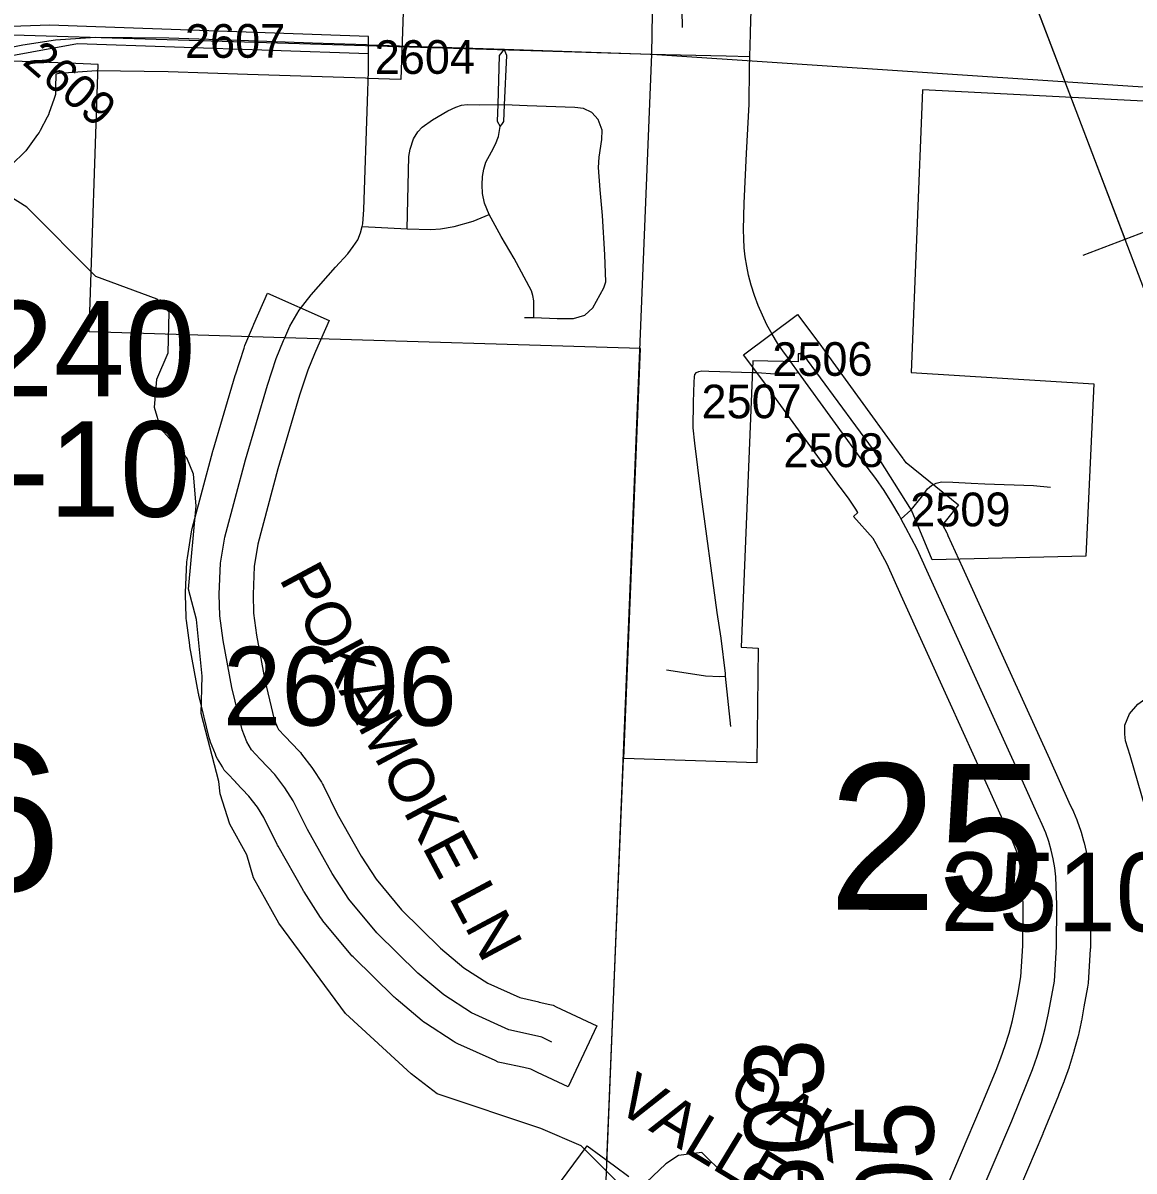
# Model space of a CAD drawing. Extents: x -132.8 to -73.3, y -60 to -26.
# Drawn here: x -123.205 to -122.216, y -43.297 to -42.275 of the extents above; entities that cross this region are included whole.
import ezdxf

# ---------------------------------------------------------------- set-up
doc = ezdxf.new("R2010")
doc.units = 0
for name, color, linetype in [('tdCoCityStreetMajor', 7, 'Continuous'), ('tdCoCityStreetMinor', 7, 'Continuous'), ('tdCoCorpBndry', 7, 'Continuous'), ('tdCoHydroRiver', 7, 'Continuous'), ('tdCoPipe', 7, 'Continuous'), ('tdCoSecRdNmbr', 7, 'Continuous'), ('tdCoSecRdTxt', 7, 'Continuous'), ('tdCoSecRteBand', 7, 'Continuous'), ('tdCoSecRteCL', 7, 'Continuous'), ('tdCoSectLine', 7, 'Continuous'), ('tdCoSectLinePart', 7, 'Continuous'), ('tdCoSectNmbr', 7, 'Continuous'), ('tdCoShieldCoRteHrd', 7, 'Continuous'), ('tdCoStrucSecCoName', 7, 'Continuous'), ('tdCoStrucSecFHWANum', 7, 'Continuous'), ('tdCoSurfAsphalt', 7, 'Continuous'), ('tdCoSurfAsphaltUnbanded', 7, 'Continuous'), ('tdCoSurfConc', 7, 'Continuous'), ('tdCoSurfGravel', 7, 'Continuous')]:
    doc.layers.add(name, color=color, linetype=linetype)

msp = doc.modelspace()

# ---------------------------------------------------------------- linework, layer by layer
at = {"layer": 'tdCoCityStreetMajor'}
for points in [[(-122.5576, -42.3052), (-122.5571, -42.2851), (-122.5567, -42.2723), (-122.5554, -42.2366), (-122.5552, -42.2089), (-122.555, -42.2038), (-122.5547, -42.1912), (-122.5544, -42.1784), (-122.5543, -42.1728), (-122.5537, -42.1347), (-122.5534, -42.1172), (-122.5531, -42.1085), (-122.5531, -42.1076)], [(-122.8973, -42.2947), (-122.8697, -42.2956), (-122.7765, -42.2988), (-122.7075, -42.301), (-122.6466, -42.303), (-122.5787, -42.3047), (-122.5576, -42.3052)], [(-122.5213, -42.5768), (-122.5221, -42.5756), (-122.5278, -42.5681), (-122.5331, -42.5603), (-122.538, -42.5522), (-122.5425, -42.5439), (-122.5466, -42.5354), (-122.5503, -42.5267), (-122.5536, -42.5178), (-122.5565, -42.5088), (-122.5589, -42.4997), (-122.5605, -42.4917), (-122.5618, -42.4836), (-122.5627, -42.4755), (-122.5632, -42.4674), (-122.5633, -42.4592), (-122.5628, -42.4358), (-122.5606, -42.3914), (-122.5584, -42.3475), (-122.5579, -42.3157), (-122.5576, -42.3052)], [(-122.5746, -42.9014), (-122.5793, -42.8566), (-122.5795, -42.8543), (-122.5834, -42.823), (-122.5869, -42.8001), (-122.6014, -42.6926), (-122.6066, -42.6494), (-122.6083, -42.6358), (-122.6079, -42.6127), (-122.6074, -42.5949), (-122.6071, -42.5902), (-122.6066, -42.5882), (-122.6051, -42.5865), (-122.603, -42.5854), (-122.6004, -42.585), (-122.5941, -42.5851), (-122.5555, -42.5864)]]:
    msp.add_lwpolyline(points, dxfattribs=at)
at = {"layer": 'tdCoCityStreetMinor'}
for p, q in [((-122.7822, -42.348), (-122.776, -42.3481)), ((-122.9029, -42.4566), (-122.8629, -42.4586)), ((-122.7582, -42.5374), (-122.7501, -42.5374))]:
    msp.add_line(p, q, dxfattribs=at)
for points in [[(-122.6177, -42.2795), (-122.6185, -42.2339), (-122.619, -42.2019)], [(-122.9029, -42.4566), (-122.9023, -42.4541), (-122.9013, -42.4415), (-122.8981, -42.3451), (-122.8971, -42.318), (-122.8973, -42.3026), (-122.8973, -42.2947)], [(-122.776, -42.3481), (-122.7742, -42.3044), (-122.7765, -42.2988), (-122.7809, -42.3043), (-122.7822, -42.348)], [(-122.8629, -42.4586), (-122.8613, -42.3943), (-122.8601, -42.3876), (-122.857, -42.3784), (-122.8534, -42.3722), (-122.8493, -42.368), (-122.8402, -42.3616), (-122.8265, -42.3536), (-122.8196, -42.3504), (-122.8143, -42.3485), (-122.8094, -42.348), (-122.7985, -42.3481), (-122.7822, -42.348)], [(-122.7822, -42.348), (-122.7826, -42.3627), (-122.7799, -42.3675)], [(-122.7799, -42.3675), (-122.7785, -42.3656), (-122.7766, -42.363), (-122.776, -42.3481)], [(-122.7501, -42.5374), (-122.7292, -42.5383), (-122.7148, -42.5384), (-122.7047, -42.5355), (-122.6974, -42.5288), (-122.6877, -42.5112), (-122.6859, -42.5057), (-122.6867, -42.4816), (-122.689, -42.4466), (-122.691, -42.4238), (-122.6924, -42.4041), (-122.692, -42.3948), (-122.6895, -42.379), (-122.6892, -42.3708), (-122.6927, -42.3614), (-122.6985, -42.3551), (-122.7059, -42.3516), (-122.7135, -42.3505), (-122.7561, -42.349), (-122.776, -42.3481)], [(-122.7898, -42.4457), (-122.7939, -42.4358), (-122.7957, -42.4272), (-122.7961, -42.4194), (-122.7957, -42.4119), (-122.7945, -42.4056), (-122.7926, -42.3991), (-122.7876, -42.3899), (-122.784, -42.3832), (-122.7814, -42.3764), (-122.7799, -42.3675)], [(-122.8629, -42.4586), (-122.8418, -42.4592), (-122.8332, -42.4585), (-122.8208, -42.4564), (-122.8041, -42.4517), (-122.7898, -42.4457)], [(-122.7501, -42.5374), (-122.75, -42.5225), (-122.7508, -42.5179), (-122.7522, -42.5138), (-122.7675, -42.4851), (-122.7791, -42.4655), (-122.7898, -42.4457)], [(-122.9717, -42.5555), (-122.9671, -42.5451), (-122.959, -42.531), (-122.9482, -42.5172), (-122.9267, -42.4926), (-122.9156, -42.4807), (-122.9107, -42.4743), (-122.9067, -42.4684), (-122.9043, -42.462), (-122.9029, -42.4566)], [(-122.414, -42.7087), (-122.405, -42.6975), (-122.3995, -42.69), (-122.3959, -42.6871), (-122.3919, -42.685), (-122.3871, -42.6838), (-122.3771, -42.684), (-122.3607, -42.685), (-122.3486, -42.6854), (-122.3052, -42.6871), (-122.2901, -42.6884)], [(-122.6318, -42.8511), (-122.6106, -42.8543), (-122.5972, -42.8563), (-122.5844, -42.8571), (-122.5793, -42.8566)]]:
    msp.add_lwpolyline(points, dxfattribs=at)
at = {"layer": 'tdCoCorpBndry'}
msp.add_lwpolyline([(-122.132, -42.3489), (-122.404, -42.3348), (-122.4142, -42.5865), (-122.2514, -42.5964), (-122.2585, -42.7499), (-122.3955, -42.7533), (-122.4139, -42.7089), (-122.4476, -42.6552), (-122.5107, -42.5699), (-122.5148, -42.5697), (-122.5148, -42.577), (-122.5551, -42.5761), (-122.5656, -42.8308), (-122.5504, -42.8319), (-122.5514, -42.9337), (-122.6699, -42.9299), (-122.6551, -42.5651), (-122.9717, -42.5555), (-123.146, -42.5502), (-123.1378, -42.3123), (-123.1577, -42.3115), (-123.2378, -42.3084), (-123.1562, -42.2935), (-122.8973, -42.3025), (-122.8973, -42.2947), (-122.8971, -42.2874), (-123.1565, -42.2783), (-123.181, -42.2772), (-123.2152, -42.2786)], dxfattribs=at)
at = {"layer": 'tdCoHydroRiver'}
for points in [[(-122.6755, -43.307), (-122.7078, -43.2746), (-122.7437, -43.2594), (-122.836, -43.2285), (-122.8592, -43.2105), (-122.9177, -43.1569), (-122.9771, -43.0764), (-122.9997, -43.0363), (-123.0054, -43.0157), (-123.0205, -42.9884), (-123.0292, -42.9614), (-123.0305, -42.9503), (-123.0462, -42.8899), (-123.0453, -42.8568), (-123.0503, -42.8062), (-123.0574, -42.7792), (-123.0507, -42.7052), (-123.0531, -42.6768), (-123.059, -42.6624), (-123.082, -42.6366), (-123.0878, -42.6175), (-123.0855, -42.5923), (-123.0755, -42.5689), (-123.0745, -42.5326), (-123.0852, -42.5213), (-123.1399, -42.5009), (-123.2014, -42.4393), (-123.2464, -42.4112)], [(-122.5807, -43.3001), (-122.6006, -43.2806), (-122.6212, -43.2832), (-122.6325, -43.2908), (-122.6616, -43.3184)]]:
    msp.add_lwpolyline(points, dxfattribs=at)
at = {"layer": 'tdCoPipe'}
msp.add_line((-122.186, -42.4535), (-122.2612, -42.4822), dxfattribs=at)
for points in [[(-119.9584, -47.7616), (-119.9471, -47.3844), (-120.3344, -46.3596), (-120.5772, -46.3668), (-120.6441, -46.2979), (-120.7015, -46.0564), (-120.837, -45.9047), (-120.8751, -45.6974), (-120.9717, -45.5088), (-121.2124, -44.6836), (-121.3801, -44.2294), (-121.5957, -43.7643), (-121.8285, -43.2571), (-122.1175, -42.7469), (-122.5487, -41.6141), (-122.6831, -41.5141), (-123.1262, -40.7823)], [(-122.2237, -42.4679), (-122.3309, -42.1863)]]:
    msp.add_lwpolyline(points, dxfattribs=at)
at = {"layer": 'tdCoSecRteBand'}
for points in [[(-122.8664, -42.2657), (-122.8683, -42.3256), (-122.8983, -42.3247), (-122.9, -42.3246), (-122.9479, -42.3231), (-122.9479, -42.3231), (-122.948, -42.3231), (-123.0049, -42.3211), (-123.0049, -42.3211), (-123.0756, -42.3187), (-123.1394, -42.3179), (-123.1726, -42.3203), (-123.1755, -42.3208), (-123.1758, -42.333), (-123.1758, -42.3344), (-123.1759, -42.3391), (-123.1774, -42.3436), (-123.1814, -42.355), (-123.1821, -42.3571), (-123.1832, -42.3592), (-123.1895, -42.371), (-123.1905, -42.3728), (-123.1917, -42.3745), (-123.2008, -42.3871), (-123.2023, -42.3892), (-123.2041, -42.391), (-123.2137, -42.4003)], [(-122.7196, -43.2222), (-122.7468, -43.2094), (-122.7528, -43.2066), (-122.7589, -43.2051), (-122.7787, -43.2007), (-122.7817, -43.2001), (-122.7845, -43.1988), (-122.8178, -43.1838), (-122.8199, -43.1828), (-122.8218, -43.1816), (-122.8465, -43.1655), (-122.848, -43.1645), (-122.8494, -43.1634), (-122.8726, -43.1439), (-122.8735, -43.1431), (-122.8743, -43.1423), (-122.9108, -43.1066), (-122.9119, -43.1055), (-122.9129, -43.1043), (-122.9377, -43.0745), (-122.9388, -43.0731), (-122.9398, -43.0716), (-122.9546, -43.0487), (-122.9551, -43.0479), (-122.9555, -43.0472), (-122.9777, -43.008), (-122.9781, -43.0072), (-122.9785, -43.0064), (-122.9903, -42.9824), (-122.9961, -42.9734), (-123.0036, -42.9635), (-123.0153, -42.9512), (-123.0153, -42.9511), (-123.0154, -42.9511), (-123.0233, -42.9427), (-123.0256, -42.9403), (-123.0273, -42.9373), (-123.0315, -42.9302), (-123.0327, -42.9282), (-123.0335, -42.926), (-123.0377, -42.9154), (-123.0385, -42.9135), (-123.039, -42.9115), (-123.0481, -42.8737), (-123.0483, -42.8729), (-123.0484, -42.8721), (-123.0561, -42.8304), (-123.0562, -42.8297), (-123.0563, -42.829), (-123.0593, -42.8071), (-123.0595, -42.8054), (-123.0595, -42.8038), (-123.06, -42.7843), (-123.06, -42.7833), (-123.06, -42.7822), (-123.0588, -42.7548), (-123.0587, -42.7531), (-123.0584, -42.7515), (-123.0547, -42.7283), (-123.0545, -42.7268), (-123.0541, -42.7253), (-123.0358, -42.6565), (-123.0357, -42.6561), (-123.0356, -42.6557), (-123.0159, -42.5891), (-123.0158, -42.5888), (-123.0157, -42.5884), (-123.008, -42.5647), (-123.0076, -42.5636), (-123.0072, -42.5624), (-123.0005, -42.5464), (-123.0004, -42.5461), (-123.0002, -42.5458), (-122.9992, -42.5433), (-122.987, -42.5159), (-122.9322, -42.5402), (-122.9443, -42.5676), (-122.9452, -42.5697), (-122.9513, -42.5843), (-122.9585, -42.6065), (-122.978, -42.6723), (-122.9957, -42.7392), (-122.9989, -42.7592), (-123, -42.7839), (-122.9996, -42.8007), (-122.9969, -42.8203), (-122.9896, -42.8604), (-122.9811, -42.8953), (-122.9786, -42.9018), (-122.9773, -42.9041), (-122.9717, -42.91), (-122.9589, -42.9235), (-122.9578, -42.9247), (-122.9568, -42.926), (-122.9476, -42.9381), (-122.947, -42.9389), (-122.9465, -42.9398), (-122.9391, -42.9511), (-122.9381, -42.9527), (-122.9372, -42.9543), (-122.9251, -42.9792), (-122.9037, -43.0169), (-122.8904, -43.0375), (-122.8677, -43.0648), (-122.8331, -43.0987), (-122.8122, -43.1162), (-122.791, -43.13), (-122.7626, -43.1428), (-122.7457, -43.1466), (-122.7455, -43.1467), (-122.7453, -43.1467), (-122.7359, -43.1489), (-122.7329, -43.1496), (-122.73, -43.151), (-122.7211, -43.1552), (-122.694, -43.168), (-122.7196, -43.2222)], [(-122.3862, -43.3205), (-122.3523, -43.2408), (-122.3386, -43.2074), (-122.3342, -43.1963), (-122.3304, -43.1854), (-122.327, -43.1744), (-122.324, -43.1632), (-122.3215, -43.152), (-122.3193, -43.1401), (-122.3164, -43.1244), (-122.3146, -43.0966), (-122.3144, -43.061), (-122.3153, -43.0376), (-122.316, -43.0315), (-122.3171, -43.0253), (-122.3185, -43.0191), (-122.3202, -43.013), (-122.3223, -43.007), (-122.3248, -43.0011), (-122.3279, -42.9946), (-122.3281, -42.9942), (-122.3283, -42.9939), (-122.3458, -42.9549), (-122.3805, -42.8783), (-122.4229, -42.7849), (-122.4356, -42.7571), (-122.4452, -42.739), (-122.4478, -42.7342), (-122.4654, -42.7146), (-122.4615, -42.711), (-122.4633, -42.7081), (-122.47, -42.6984), (-122.4774, -42.6885), (-122.4775, -42.6884), (-122.4776, -42.6882), (-122.5387, -42.6039), (-122.5454, -42.5946), (-122.5633, -42.5707), (-122.5152, -42.5348), (-122.4972, -42.5589), (-122.4972, -42.5589), (-122.4971, -42.559), (-122.497, -42.5592), (-122.4901, -42.5687), (-122.4291, -42.6528), (-122.4216, -42.663), (-122.4212, -42.6634), (-122.4209, -42.6639), (-122.4188, -42.6669), (-122.4185, -42.6665), (-122.3719, -42.7042), (-122.3862, -42.722), (-122.3824, -42.7291), (-122.3825, -42.7292), (-122.3822, -42.7297), (-122.3818, -42.7305), (-122.3814, -42.7314), (-122.3683, -42.76), (-122.3683, -42.76), (-122.3683, -42.76), (-122.3259, -42.8535), (-122.3259, -42.8535), (-122.3259, -42.8535), (-122.2911, -42.9302), (-122.2911, -42.9302), (-122.2911, -42.9303), (-122.2737, -42.9689), (-122.2704, -42.9757), (-122.27, -42.9765), (-122.2697, -42.9773), (-122.2666, -42.9847), (-122.2663, -42.9855), (-122.266, -42.9863), (-122.2633, -42.9939), (-122.2631, -42.9947), (-122.2628, -42.9955), (-122.2606, -43.0032), (-122.2604, -43.004), (-122.2602, -43.0049), (-122.2584, -43.0127), (-122.2582, -43.0135), (-122.258, -43.0144), (-122.2567, -43.0223), (-122.2566, -43.0231), (-122.2565, -43.024), (-122.2556, -43.032), (-122.2554, -43.033), (-122.2554, -43.0341), (-122.2544, -43.0593), (-122.2544, -43.06), (-122.2544, -43.0607), (-122.2546, -43.0979), (-122.2546, -43.0988), (-122.2547, -43.0997), (-122.2567, -43.13), (-122.2568, -43.1317), (-122.2571, -43.1334), (-122.2603, -43.151), (-122.2603, -43.151), (-122.2603, -43.151), (-122.2626, -43.1635), (-122.2627, -43.1641), (-122.2629, -43.1646), (-122.2656, -43.177), (-122.2658, -43.1776), (-122.2659, -43.1781), (-122.2692, -43.1904), (-122.2693, -43.1909), (-122.2695, -43.1915), (-122.2732, -43.2036), (-122.2734, -43.2042), (-122.2736, -43.2047), (-122.2778, -43.2167), (-122.278, -43.2172), (-122.2782, -43.2178), (-122.2829, -43.2296), (-122.2829, -43.2297), (-122.283, -43.2299), (-122.2968, -43.2637), (-122.2969, -43.2639), (-122.297, -43.2641), (-122.331, -43.344)], [(-122.7381, -43.3228), (-122.7024, -43.2746), (-122.6783, -43.2924), (-122.6654, -43.302)]]:
    msp.add_lwpolyline(points, dxfattribs=at)
at = {"layer": 'tdCoSecRteCL'}
for points in [[(-123.2049, -42.2947), (-123.1758, -42.2905), (-123.1403, -42.2879), (-123.0749, -42.2887), (-123.0039, -42.2911), (-122.9469, -42.2931), (-122.899, -42.2946), (-122.8973, -42.2947)], [(-122.7339, -43.1823), (-122.7428, -43.1781), (-122.7522, -43.1759), (-122.7722, -43.1715), (-122.8055, -43.1564), (-122.8301, -43.1404), (-122.8533, -43.1209), (-122.8898, -43.0851), (-122.9146, -43.0553), (-122.9294, -43.0324), (-122.9516, -42.9932), (-122.9642, -42.9675), (-122.9716, -42.9562), (-122.9807, -42.9441), (-122.9935, -42.9305), (-123.0014, -42.9222), (-123.0056, -42.915), (-123.0098, -42.9044), (-123.0189, -42.8667), (-123.0266, -42.825), (-123.0295, -42.803), (-123.03, -42.7836), (-123.0288, -42.7562), (-123.0251, -42.733), (-123.0068, -42.6642), (-122.9871, -42.5976), (-122.9795, -42.5739), (-122.9728, -42.5579), (-122.9717, -42.5555)], [(-122.5144, -42.5863), (-122.5213, -42.5768), (-122.5213, -42.5768)], [(-122.5555, -42.5864), (-122.5511, -42.5865), (-122.5356, -42.5875), (-122.5267, -42.5873), (-122.5198, -42.5873), (-122.5144, -42.5863)], [(-122.4231, -42.7169), (-122.4249, -42.7135), (-122.4314, -42.7024), (-122.4383, -42.6915), (-122.4456, -42.6809), (-122.4533, -42.6706), (-122.5144, -42.5863)], [(-122.4231, -42.7169), (-122.4229, -42.7167), (-122.4144, -42.7091), (-122.414, -42.7087)], [(-122.3586, -43.3322), (-122.3246, -43.2523), (-122.3108, -43.2185), (-122.3061, -43.2067), (-122.3019, -43.1948), (-122.2982, -43.1827), (-122.2949, -43.1704), (-122.2921, -43.158), (-122.2898, -43.1455), (-122.2866, -43.128), (-122.2846, -43.0977), (-122.2844, -43.0605), (-122.2854, -43.0353), (-122.2863, -43.0273), (-122.2876, -43.0194), (-122.2894, -43.0115), (-122.2917, -43.0038), (-122.2943, -42.9962), (-122.2974, -42.9888), (-122.3009, -42.9816), (-122.3184, -42.9426), (-122.3532, -42.8659), (-122.3956, -42.7724), (-122.4087, -42.7438), (-122.4188, -42.7248), (-122.4231, -42.7169)]]:
    msp.add_lwpolyline(points, dxfattribs=at)
at = {"layer": 'tdCoSectLine'}
for points in [[(-122.6449, -42.303), (-122.6291, -41.3247)], [(-123.6452, -42.2728), (-122.6449, -42.303)], [(-122.6865, -43.3276), (-122.6449, -42.303)], [(-122.6449, -42.303), (-121.6589, -42.3688)]]:
    msp.add_lwpolyline(points, dxfattribs=at)
at = {"layer": 'tdCoSectLinePart'}
msp.add_lwpolyline([(-122.6849, -43.2877), (-122.6703, -42.9299)], dxfattribs=at)
at = {"layer": 'tdCoShieldCoRteHrd'}
msp.add_lwpolyline([(-122.1373, -43.2102), (-122.2193, -42.9273), (-122.2232, -42.9141), (-122.2239, -42.9082), (-122.2239, -42.9004), (-122.2197, -42.8901), (-122.2124, -42.8816), (-122.2028, -42.8749), (-122.0355, -42.8026), (-122.028, -42.801), (-122.0176, -42.8), (-122.0072, -42.801), (-121.9996, -42.8026), (-121.8324, -42.8749), (-121.8228, -42.8816), (-121.8155, -42.8901), (-121.8113, -42.9004), (-121.8113, -42.9082), (-121.812, -42.9141), (-121.8159, -42.9273), (-121.8978, -43.2102)], close=True, dxfattribs=at)
at = {"layer": 'tdCoSurfAsphalt'}
for points in [[(-124.4259, -42.6681), (-124.3933, -42.6566), (-124.3297, -42.6324), (-124.2453, -42.6009), (-124.1785, -42.575), (-124.0544, -42.5371), (-123.957, -42.509), (-123.7734, -42.4546), (-123.7729, -42.4545), (-123.5774, -42.3972), (-123.5381, -42.3858), (-123.5343, -42.3847), (-123.3155, -42.3216), (-123.2697, -42.3091), (-123.2332, -42.3005), (-123.2049, -42.2947), (-123.1758, -42.2905), (-123.1403, -42.2879), (-123.0749, -42.2887), (-123.0039, -42.2911), (-122.9469, -42.2931), (-122.899, -42.2946), (-122.8973, -42.2947)], [(-122.3586, -43.3322), (-122.3246, -43.2523), (-122.3108, -43.2185), (-122.3061, -43.2067), (-122.3019, -43.1948), (-122.2982, -43.1827), (-122.2949, -43.1704), (-122.2921, -43.158), (-122.2898, -43.1455), (-122.2866, -43.128), (-122.2846, -43.0977), (-122.2844, -43.0605), (-122.2854, -43.0353), (-122.2863, -43.0273), (-122.2876, -43.0194), (-122.2894, -43.0115), (-122.2917, -43.0038), (-122.2943, -42.9962), (-122.2974, -42.9888), (-122.3009, -42.9816), (-122.3184, -42.9426), (-122.3532, -42.8659), (-122.3956, -42.7724), (-122.4087, -42.7438), (-122.4188, -42.7248), (-122.4231, -42.7169), (-122.4249, -42.7135), (-122.4314, -42.7024), (-122.4383, -42.6915), (-122.4456, -42.6809), (-122.4533, -42.6706), (-122.5144, -42.5863), (-122.5213, -42.5768), (-122.5213, -42.5768)]]:
    msp.add_lwpolyline(points, dxfattribs=at)
at = {"layer": 'tdCoSurfAsphaltUnbanded'}
msp.add_lwpolyline([(-122.5555, -42.5864), (-122.5511, -42.5865), (-122.5356, -42.5875), (-122.5267, -42.5873), (-122.5198, -42.5873), (-122.5144, -42.5863)], dxfattribs=at)
at = {"layer": 'tdCoSurfConc'}
msp.add_lwpolyline([(-122.4231, -42.7169), (-122.4229, -42.7167), (-122.4144, -42.7091), (-122.414, -42.7087)], dxfattribs=at)
at = {"layer": 'tdCoSurfGravel'}
msp.add_lwpolyline([(-122.7339, -43.1823), (-122.7428, -43.1781), (-122.7522, -43.1759), (-122.7722, -43.1715), (-122.8055, -43.1564), (-122.8301, -43.1404), (-122.8533, -43.1209), (-122.8898, -43.0851), (-122.9146, -43.0553), (-122.9294, -43.0324), (-122.9516, -42.9932), (-122.9642, -42.9675), (-122.9716, -42.9562), (-122.9807, -42.9441), (-122.9935, -42.9305), (-123.0014, -42.9222), (-123.0056, -42.915), (-123.0098, -42.9044), (-123.0189, -42.8667), (-123.0266, -42.825), (-123.0295, -42.803), (-123.03, -42.7836), (-123.0288, -42.7562), (-123.0251, -42.733), (-123.0068, -42.6642), (-122.9871, -42.5976), (-122.9795, -42.5739), (-122.9728, -42.5579), (-122.9717, -42.5555)], dxfattribs=at)

# ---------------------------------------------------------------- texts
at = {"layer": 'tdCoSecRdNmbr'}
for s, height, rotation, p in [('2607', 0.03, 0.1814, (-123.0605, -42.3065)), ('2604', 0.03, 0.1814, (-122.8916, -42.3208)), ('2609', 0.03, 319.2294, (-123.2062, -42.3114)), ('2506', 0.03, 0.1814, (-122.5377, -42.5896)), ('2507', 0.03, 0.1814, (-122.6007, -42.6273)), ('2508', 0.03, 0.1814, (-122.5278, -42.6708)), ('2509', 0.03, 0.1814, (-122.4149, -42.7235)), ('2606', 0.07, 359.908, (-123.0269, -42.9005)), ('2510', 0.07, 359.909, (-122.3882, -43.0835)), ('3603', 0.07, 89.9083, (-122.4926, -43.3877)), ('3605', 0.07, 89.9083, (-122.3943, -43.4432))]:
    msp.add_text(s, height=height, rotation=rotation, dxfattribs=at).set_placement(p)
at = {"layer": 'tdCoSecRdTxt'}
for s, rotation, p in [('POKAMOKE LN', 298.0825, (-122.9773, -42.7698)), ('VALLEY RD', 328.7264, (-122.6792, -43.2419)), ('OAK', 328.7264, (-122.5793, -43.2324))]:
    msp.add_text(s, height=0.04, rotation=rotation, dxfattribs=at).set_placement(p)
at = {"layer": 'tdCoSectNmbr'}
for s, rotation, p in [('26', 359.9077, (-123.3644, -43.0476)), ('25', 359.9085, (-122.4879, -43.0646))]:
    msp.add_text(s, height=0.13, rotation=rotation, dxfattribs=at).set_placement(p)
at = {"layer": 'tdCoStrucSecCoName'}
msp.add_text('CR-10', height=0.085, dxfattribs=at).set_placement((-123.3837, -42.7148))
at = {"layer": 'tdCoStrucSecFHWANum'}
msp.add_text('289240', height=0.085, dxfattribs=at).set_placement((-123.4304, -42.6077))

doc.saveas('drawing.dxf')
